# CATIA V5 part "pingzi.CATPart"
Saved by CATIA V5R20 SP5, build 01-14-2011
Part number: Part1
Material "DS Dark Green": density 7860 kg/m3, Young's modulus 2e+11 Pa, Poisson ratio 0.266
Bounding box of the stored display mesh (mm): x -25 to 25, y -25 to 25, z 0 to 110
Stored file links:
  E:\180212220\pingzi.CATPart
  C:\Program Files\Dassault Systemes\B20\intel_a\startup\materials\Catalog.CATMaterial
  C:\Program Files\Dassault Systemes\B20\intel_a\startup\materials\green_env_512x512.jpg
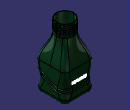
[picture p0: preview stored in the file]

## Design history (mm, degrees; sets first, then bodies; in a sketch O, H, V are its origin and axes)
Set1
  Sketch1 on xy-plane, origin (0, 0, 0), H (1, 0, 0), V (0, 1, 0)
    line L1 (25, 25) -> (25, -25)
    line L2 (25, -25) -> (-25, -25)
    line L3 (-25, -25) -> (-25, 25)
    line L4 (-25, 25) -> (25, 25)
    distance L2 L4 = 50
    distance L1 L3 = 50
    vertical: L1 V, L3 V
    horizontal: L2 H, L4 H
    equidistance: L1 L3 O, L2 L4 O
  Sketch2 on face of Pad1 from Sketch1.L1, origin (25, 0, 0), H (0, 1, 0), V (0, 0, 1)
    spline S1 through (-41.0208, 19.1785) (-23.8194, 29.3752) (5.3146, 19.1785) (39.2526, 27.8303)
  Extrude1: Element1 Sketch2, Lim1 100, Lim2 100
  MultiSel1: CommonCtxFeats ({extract ExtractElem face of Fillet1}; {extract ExtractElem face of Pad1 from Sketch1.L4}; {extract ExtractElem face of Fillet1}; {extract ExtractElem face of Pad1 from Sketch1.L3}; {extract ExtractElem face of Fillet1}; {extract ExtractElem face of Pad1 from Sketch1.L2}; {extract ExtractElem face of Fillet1}; {extract ExtractElem face of Pad1 from Sketch1.L1})
  Sketch3 on face of Pad1 from Sketch1.L3, origin (-25, 0, 0), H (0, -1, 0), V (0, 0, 1)
    spline S1 through (-29.1754, 26.7043) (-15.4565, 22.3207) (12.3331, 33.3675) (30.625, 35.121)
  Extrude2: Element1 Sketch3, Lim1 100, Lim2 100
  MultiSel2: CommonCtxFeats ({extract ExtractElem face of Pad1 from Sketch1.L3}; {extract ExtractElem face of Fillet1}; {extract ExtractElem face of Pad1 from Sketch1.L2}; {extract ExtractElem face of Fillet1}; {extract ExtractElem face of Pad1 from Sketch1.L1}; {extract ExtractElem face of Fillet1}; {extract ExtractElem face of Pad1 from Sketch1.L4}; {extract ExtractElem face of Fillet1})
  Join1: Elements ({intersect ToIntersect1 {extract ExtractElem face of Pad1 from Sketch1.L1}, ToIntersect2 Extrude2}; {intersect ToIntersect1 {extract ExtractElem face of Fillet1}, ToIntersect2 Extrude2}; {intersect ToIntersect1 {extract ExtractElem face of Pad1 from Sketch1.L4}, ToIntersect2 Extrude2}; {intersect ToIntersect1 {extract ExtractElem face of Fillet1}, ToIntersect2 Extrude2}; {intersect ToIntersect1 {extract ExtractElem face of Pad1 from Sketch1.L3}, ToIntersect2 Extrude2}; {intersect ToIntersect1 {extract ExtractElem face of Fillet1}, ToIntersect2 Extrude2}; {intersect ToIntersect1 {extract ExtractElem face of Pad1 from Sketch1.L2}, ToIntersect2 Extrude2}; {intersect ToIntersect1 {extract ExtractElem face of Fillet1}, ToIntersect2 Extrude2})
  Join2: Elements ({intersect ToIntersect1 {extract ExtractElem face of Pad1 from Sketch1.L1}, ToIntersect2 Extrude1}; {intersect ToIntersect1 {extract ExtractElem face of Fillet1}, ToIntersect2 Extrude1}; {intersect ToIntersect1 {extract ExtractElem face of Pad1 from Sketch1.L4}, ToIntersect2 Extrude1}; {intersect ToIntersect1 {extract ExtractElem face of Fillet1}, ToIntersect2 Extrude1}; {intersect ToIntersect1 {extract ExtractElem face of Pad1 from Sketch1.L3}, ToIntersect2 Extrude1}; {intersect ToIntersect1 {extract ExtractElem face of Fillet1}, ToIntersect2 Extrude1}; {intersect ToIntersect1 {extract ExtractElem face of Pad1 from Sketch1.L2}, ToIntersect2 Extrude1}; {intersect ToIntersect1 {extract ExtractElem face of Fillet1}, ToIntersect2 Extrude1})
  Plane1: type Normal, Curve Join1, RefPoint vertex [face of MultiSel2 | face of MultiSel2]
  Sketch4 on Plane1, origin (0, 7.2514, -1.4258), H (-1, 0, 0), V (0, 0.1929, 0.9812)
    circle A1 centre (-24.9405, 24.7394) radius 1
    radius A1 = 1
  Plane2: type Normal, Curve Join2, RefPoint vertex [face of MultiSel1 | face of MultiSel1]
  Sketch5 on Plane2, origin (0, 10.2539, -1.3853), H (-1, 0, 0), V (0, 0.1339, 0.991)
    circle A1 centre (-24.8669, 18.9887) radius 1
    radius A1 = 1
Body1 (main body), material "DS Dark Green"
  Pad1: profile Sketch1, direction (0, 0, 1), length 50
  Fillet1: on edge [face of Pad1 from Sketch1.L2 | face of Pad1 from Sketch1.L3]; edge [face of Pad1 from Sketch1.L1 | face of Pad1 from Sketch1.L2]; edge [face of Pad1 from Sketch1.L3 | face of Pad1 from Sketch1.L4]; edge [face of Pad1 from Sketch1.L4 | face of Pad1 from Sketch1.L1]
  Fillet2: radius 8, on start face of Pad1
  Plane3: type Offset, RefPlane end face of Pad1, Offset 40, reversed
  Sketch6 on Plane3, origin (0, 0, 90), H (1, 0, 0), V (0, -1, 0)
    circle A1 centre (0, 0) radius 15
    radius A1 = 15
  Pad2: profile Sketch6, direction (0, 0, -1), length -20
  Sketch7 on end face of Pad1, origin (0, 0, 50), H (1, 0, 0), V (0, 1, 0)
    point P1 (25, 0)
    distance P1 V = 25
    coincidence: P1 H
  Sketch8 on start face of Pad2, origin (0, 0, 90), H (1, 0, 0), V (0, -1, 0)
  Sketch9 on start face of Pad2, origin (0, 0, 90), H (1, 0, 0), V (0, -1, 0)
  Sketch10 on start face of Pad2, origin (0, 0, 90), H (1, 0, 0), V (0, -1, 0)
    point P1 (15, 0)
    distance P1 V = 15
    distance P1 H = 0
  Loft1: solid, Sections ({boundary Boundary {extract ExtractElem end face of Pad1}}; {boundary Boundary {extract ExtractElem start face of Pad2}}), StartFace end face of Pad1, EndFace start face of Pad2
  Slot1: profile Sketch4, centre curve Join1
  Slot2: profile Sketch5, centre curve Join2
  Shell1: ExtOffset 0, Face end face of Pad2, IntOffset 1
  Plane4: type Offset, RefPlane Plane3, Offset -2
  Sketch11 on Plane4, origin (0, 0, 92), H (1, 0, 0), V (0, -1, 0)
    point P1 (15, 0)
    distance P1 V = 15
    distance P1 H = 0
  Helix1: Direction Z axis, RefPoint Sketch11, Pitch 3, Height 16, TaperAngle 0
  Point1: type OnCurve, Support Helix1, Length 5.262
  Line1: type PtDir, RefPoint Sketch11, Direction (1, 0, 0), Start 0, End 10
  Connect1: Curve1 Line1, Point1 vertex of Line1, Tension1 1, Curve2 Helix1, Point2 Point1, Tension2 1
  Line2: type PtDir, RefPoint vertex of Helix1, Direction (0, 1, 0), Start 0, End -10
  Point2: type OnCurve, Support Connect1, Length 500.359
  Connect2: Curve1 Line2, Point1 vertex of Line2, Tension1 1, Curve2 Connect1, Point2 Point2, Tension2 1
  Plane5: type Normal, Curve Connect2, RefPoint {point type OnCurve, Support Connect2, Ratio 0}
  Sketch12 on Plane5, origin (0, 2.9904, 0), H (-1, 0, 0), V (0, 0, 1)
    circle A1 centre (7.5041, 108.0117) radius 0.5
    radius A1 = 0.5
  Rib1: profile Sketch12, centre curve Connect2
  Body2
    Sketch13 on Plane3, origin (0, 0, 90), H (1, 0, 0), V (0, -1, 0)
      circle A1 centre (0, 0) radius 14
      radius A1 = 14
    Pad3: profile Sketch13, direction (0, 0, -1), length -30
  Remove1: tool Body2
  Body3
  Remove2: tool Body3
  Body4
  Remove3: tool Body4
  Sketch14 on face of Pad1 from Sketch1.L4, origin (0, 25, 0), H (-1, 0, 0), V (0, 0, 1)
    polyline C1
    polyline C2
    polyline C3
    polyline C4
    polyline C5
    polyline C6
    polyline C7
    polyline C8
    polyline C9
    polyline C10
    polyline C11
    polyline C12
    polyline C13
